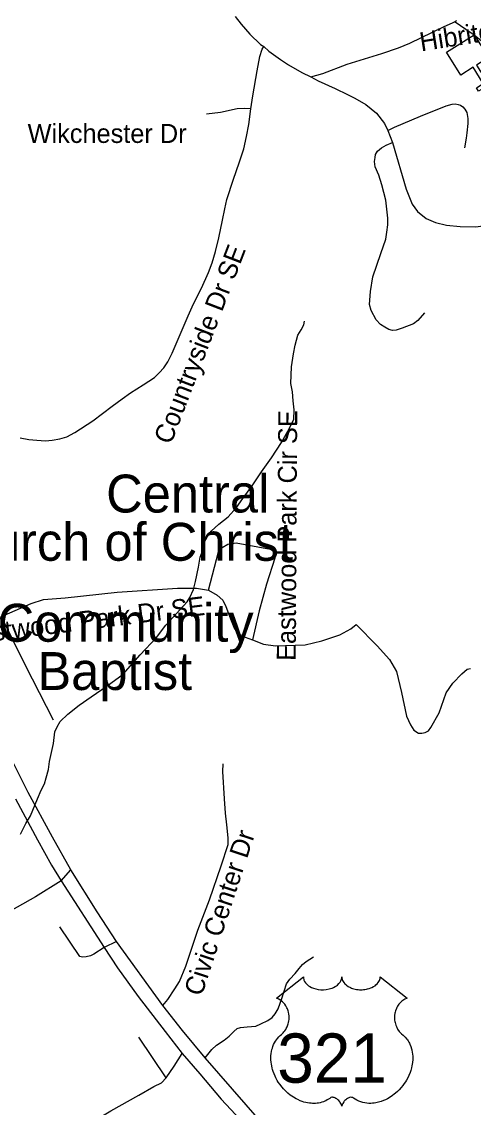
# Model space of a CAD drawing. Extents: x 1159738 to 1321356, y 736314 to 882035.
# Drawn here: x 1255384 to 1257173, y 783980 to 788278 of the extents above; entities that cross this region are included whole.
import ezdxf

# ---------------------------------------------------------------- set-up
doc = ezdxf.new("R2010")
doc.units = 0
for name, color, linetype in [('Exist Cultural Church CELL', 7, 'Continuous'), ('Exist Cultural Church Label', 7, 'Continuous'), ('Exist Hydrographic Misc Water Feature', 7, 'Continuous'), ('Exist Road Non-System Type 51', 7, 'Continuous'), ('Exist Road Non-System Type 51 Label', 7, 'Continuous'), ('Exist Road Primary US Divided Attributed', 7, 'Continuous'), ('Exist Road Primary US Shield CELL', 7, 'Continuous'), ('Exist Road Primary US Shield Number Label', 7, 'Continuous'), ('Exist Road Secondary Type 51 Attributed', 7, 'Continuous'), ('Exist Road Secondary Type 51 Label', 7, 'Continuous')]:
    doc.layers.add(name, color=color, linetype=linetype)

msp = doc.modelspace()

# ---------------------------------------------------------------- linework, layer by layer
at = {"layer": 'Exist Cultural Church CELL'}
msp.add_lwpolyline([(1257233.6, 788135.9), (1257185.5, 788105.5), (1257226, 788041.1), (1257253.1, 788058.1), (1257261.6, 788044.6), (1257234.5, 788027.5), (1257266.5, 787976.6), (1257252.9, 787968.1), (1257220.9, 788019), (1257193.8, 788002), (1257185.3, 788015.5), (1257212.4, 788032.5), (1257171.9, 788097), (1257123, 788066.4), (1257066.4, 788156.5), (1257177, 788226)], close=True, dxfattribs=at)
at = {"layer": 'Exist Hydrographic Misc Water Feature'}
msp.add_lwpolyline([(1255378.9, 785061.3), (1255400, 785102.8), (1255418.8, 785134.3), (1255446.5, 785201.6), (1255461.3, 785235.3), (1255474.1, 785261), (1255480.7, 785284.8), (1255489.5, 785316.6), (1255494.3, 785348.5), (1255510.2, 785420.1), (1255515.3, 785466.1), (1255523.9, 785485.8), (1255536.5, 785507.5), (1255567.2, 785536.7), (1255612.2, 785571.7), (1255659.1, 785604.5), (1255722.2, 785648.8), (1255785.5, 785695.2), (1255853.5, 785771.5), (1255917.4, 785839.9), (1255954.6, 785889), (1256024.6, 785965.2), (1256038.9, 785980.9), (1256049.5, 785998.6), (1256064.4, 786030.3), (1256073.1, 786062), (1256084.6, 786117.8), (1256091.6, 786157.6), (1256102.5, 786189.4), (1256107.1, 786215.3), (1256119.7, 786239), (1256134.3, 786260.6), (1256165, 786287.8), (1256201.9, 786316.9), (1256234.7, 786354.1), (1256259.7, 786389.5), (1256297.1, 786440.6), (1256334.4, 786495.6), (1256374, 786550.6), (1256413.5, 786611.6), (1256426.1, 786635.3), (1256445, 786668.8), (1256453.6, 786688.7), (1256461.9, 786702.4), (1256462.8, 786740.4), (1256459.8, 786776.5), (1256456.7, 786812.7), (1256449.6, 786844.9), (1256453.3, 786910.8), (1256460.6, 786962.7), (1256467.5, 786996.5), (1256478.5, 787036.2), (1256491.1, 787057.9), (1256501.5, 787077.7), (1256504, 787091.6)], dxfattribs=at)
at = {"layer": 'Exist Road Non-System Type 51'}
for p, q in [((1255956.1, 784096.6), (1255848.5, 784257.6)), ((1255987.8, 784142.8), (1256020.1, 784193.4)), ((1255956.1, 784096.6), (1255987.8, 784142.8))]:
    msp.add_line(p, q, dxfattribs=at)
for points in [[(1257100.9, 788276.4), (1257143.2, 788247.5), (1257176.8, 788225.3), (1257218.4, 788191.1), (1257296.3, 788125.2), (1257349.3, 788077.5), (1257394.9, 788037.9), (1257423.8, 788019.1), (1257451.3, 787994.9), (1257464.8, 787976.8), (1257470.1, 787962), (1257474.1, 787945.6), (1257477.4, 787922.8), (1257477.4, 787895.2), (1257473.4, 787875.8)], [(1256292.3, 787932.3), (1256299, 787984.4), (1256317.2, 788083.2), (1256327.2, 788140), (1256336.6, 788168.2), (1256343.3, 788179)], [(1255378.2, 786630.3), (1255412.5, 786623.6), (1255444, 786620.3), (1255478.9, 786618.9), (1255505.1, 786620.9), (1255535.3, 786626.3), (1255562.2, 786634.4), (1255595.1, 786651.8), (1255665.5, 786696.8), (1255741.9, 786755.1), (1255782.1, 786784.7), (1255815, 786808.9), (1255864.7, 786840.4), (1255910, 786869), (1255928.8, 786887.1), (1255947, 786907.3), (1255963.1, 786931.5), (1255979.8, 786965.1), (1256007.4, 787030.2), (1256042.9, 787113.5), (1256065, 787160.9), (1256095.9, 787222.7), (1256123.4, 787285.2), (1256138.8, 787323), (1256151.5, 787367.3), (1256164.9, 787421.8), (1256179, 787492.3), (1256188.4, 787536.6), (1256197.2, 787574.2), (1256222.6, 787653.8), (1256245.4, 787719), (1256263.5, 787774.1), (1256274.9, 787823.5), (1256283.6, 787870.5), (1256292.3, 787932.3)], [(1256292.3, 787932.3), (1256266.9, 787934.1), (1256238, 787932.8), (1256170.9, 787918.6), (1256115.9, 787911.9)], [(1256834.5, 787847.4), (1256861, 787859.7), (1256963.2, 787903.6), (1257065.9, 787945), (1257089.8, 787951.3), (1257101.5, 787951.8), (1257112.7, 787950.3), (1257121.9, 787947.4), (1257131.1, 787940.6), (1257138.9, 787930.8), (1257147.2, 787918.2), (1257151.6, 787894.3), (1257151.1, 787874.8), (1257147.7, 787837.3), (1257145.3, 787816.4), (1257137.5, 787778.8)], [(1256979.4, 787125.4), (1256953.6, 787094.2), (1256936.6, 787082), (1256890.8, 787064.5), (1256867, 787056.2), (1256853.4, 787055.2), (1256837.8, 787058.6), (1256822.7, 787067.9), (1256805.2, 787079.1), (1256788.1, 787097.1), (1256768.2, 787133.7), (1256761.8, 787158.5), (1256766.2, 787209.2), (1256775, 787268.1), (1256807.1, 787360.2), (1256827.1, 787416.7), (1256831, 787445), (1256833.9, 787473.7), (1256834.4, 787500), (1256831.5, 787523.4), (1256826.1, 787571.3), (1256810.5, 787632.2), (1256799.3, 787669.7), (1256784.2, 787703.3), (1256781.8, 787724.2), (1256783.8, 787740.3), (1256786.2, 787752), (1256793.5, 787764.9), (1256809.1, 787778.5), (1256828, 787788.8), (1256852.4, 787799.5)], [(1256124.3, 786027.3), (1256163.9, 786179.1), (1256178.7, 786196), (1256200.2, 786209), (1256233.7, 786214.2), (1256369.3, 786189.5), (1256384.1, 786180.4), (1256388.1, 786169.9), (1256386.8, 786154.3), (1256353.2, 786051.4), (1256325, 785945.9), (1256298.2, 785829.9)], [(1255191.1, 785872.2), (1255292.9, 785918.3), (1255422, 785973.9), (1255470.4, 785989.5), (1255556.3, 785997.3), (1255761.7, 786019.5), (1256000.8, 786035.1), (1256076, 786035.1), (1256124.3, 786027.3)], [(1256124.3, 786027.3), (1256158.5, 786007.1), (1256181.4, 785987.5), (1256192.1, 785962.8), (1256213.6, 785906.8), (1256227, 785874.2), (1256244.5, 785854.7), (1256268.6, 785841.6), (1256298.2, 785829.9)], [(1255292.9, 785918.3), (1255315.7, 785896.3), (1255344.6, 785836.5), (1255397.1, 785729.6), (1255509, 785513.5)], [(1256298.2, 785829.9), (1256342.5, 785813), (1256389.5, 785806.4), (1256506.3, 785810.4), (1256573.4, 785826), (1256643.9, 785850.1), (1256688.3, 785873.5), (1256708.8, 785890.6)], [(1256708.8, 785890.6), (1256791.9, 785807.2), (1256841.2, 785752.8), (1256868.1, 785705), (1256888.2, 785622.3), (1256908.4, 785528.8), (1256924.1, 785494), (1256937.5, 785472.3), (1256955.4, 785461.4), (1256968.9, 785461.4), (1256982.3, 785463.6), (1256995.8, 785470.1), (1257004.7, 785483.1), (1257038.4, 785541.9), (1257065.2, 785620.2), (1257092.1, 785659.3), (1257128, 785696.3), (1257148.2, 785713.7), (1257161.9, 785716.6)], [(1255943, 784383.3), (1255962.8, 784406.9), (1255990.8, 784448.2), (1256009.2, 784477.6), (1256034.2, 784538), (1256082.1, 784680.9), (1256127.5, 784801.3), (1256173.9, 784935.3), (1256201.8, 785020.4), (1256202.5, 785046.2), (1256196.6, 785098.5), (1256190.7, 785144.9), (1256187, 785200.9), (1256180.4, 785309.4), (1256182.6, 785339.5)], [(1255540.7, 784876.8), (1255579, 784920.2)], [(1255540.7, 784876.8), (1255439.1, 784813.4), (1255291.4, 784731.3)], [(1255710.4, 784612.3), (1255669.9, 784585.8), (1255656.7, 784579.1), (1255639, 784575.5), (1255624.3, 784574), (1255614.7, 784576.9), (1255534.5, 784694)], [(1255759.7, 784636.6), (1255710.4, 784612.3)], [(1256111.4, 784175.4), (1256137.1, 784209.2), (1256155.5, 784225.4), (1256185.7, 784246.1), (1256205.6, 784261.5), (1256224, 784279.9), (1256237.2, 784291.7), (1256250.5, 784296.2), (1256277.7, 784298.4), (1256311.6, 784301.3), (1256330.7, 784310.9), (1256358.7, 784323.4), (1256376.3, 784335.9), (1256388.6, 784349.7), (1256399.6, 784369.6), (1256414.3, 784410.8), (1256432.7, 784468.3), (1256446.7, 784486.7), (1256467.3, 784509.5), (1256483.5, 784529.4), (1256496, 784544.9), (1256511.5, 784556.7), (1256540.2, 784575.1)], [(1255602, 783885.7), (1255736.7, 783965.2), (1255848.1, 784028.3), (1255908, 784061.6), (1255937.4, 784077), (1255956.1, 784096.6)]]:
    msp.add_lwpolyline(points, dxfattribs=at)
at = {"layer": 'Exist Road Primary US Divided Attributed'}
for points in [[(1256326.9, 783927), (1256111.4, 784175.4), (1256020.7, 784284.4), (1255943, 784383.3), (1255759.7, 784636.6), (1255683.2, 784754.3), (1255579, 784920.2), (1255505.4, 785048.9), (1255409.1, 785226), (1255337, 785371.1), (1255253.6, 785532.1), (1255166.7, 785714.4), (1255144.5, 785758.2), (1255037, 785979.7), (1254900.5, 786258.5), (1254752.6, 786556.6), (1254651, 786761.2), (1254574, 786916.1), (1254464.3, 787134.7), (1254340.1, 787387.7), (1254244.7, 787573.2), (1254139.2, 787789.1), (1254097.8, 787873.2)], [(1255360, 785201.6), (1255446.5, 785038.1), (1255502.3, 784938.3), (1255540.7, 784876.8), (1255710.4, 784612.3), (1255763.4, 784531.6), (1255845.1, 784418.5), (1255952.7, 784279.3), (1256020.1, 784193.4), (1256089.2, 784112.8), (1256174.4, 784012.2), (1256306.9, 783869.3)]]:
    msp.add_lwpolyline(points, dxfattribs=at)
at = {"layer": 'Exist Road Primary US Shield CELL'}
msp.add_lwpolyline([(1256500, 784496), (1256500.3, 784491.6), (1256501.4, 784486.4), (1256502.2, 784483.7), (1256504.7, 784478.5), (1256508.7, 784472.5), (1256514.3, 784466.5), (1256520.6, 784461.3), (1256524.9, 784458.5), (1256532.1, 784454.6), (1256540.4, 784451.2), (1256549.5, 784448.5), (1256558.9, 784446.6), (1256569.1, 784445.5), (1256579.2, 784445.3), (1256590.1, 784446.1), (1256602.2, 784448.5), (1256607.8, 784449.9), (1256614, 784452), (1256619.8, 784454.4), (1256626.1, 784457.8), (1256631.2, 784461.1), (1256635.2, 784464), (1256640.8, 784469.4), (1256645.3, 784475), (1256647.2, 784478.1), (1256648.8, 784481.1), (1256651.1, 784487.5), (1256651.7, 784490.4), (1256652.1, 784496.2), (1256652.5, 784491.3), (1256653, 784488.2), (1256653.8, 784485.2), (1256655.1, 784482), (1256657.3, 784477.5), (1256659.8, 784473.7), (1256664.6, 784468.1), (1256667.5, 784465.4), (1256670.2, 784463.2), (1256677.5, 784458.2), (1256685.9, 784453.9), (1256690, 784452.1), (1256694.3, 784450.6), (1256699.7, 784449), (1256705.3, 784447.7), (1256710.8, 784446.7), (1256716.5, 784445.9), (1256722.2, 784445.5), (1256726.9, 784445.3), (1256732.7, 784445.4), (1256738.1, 784445.7), (1256743.5, 784446.3), (1256749.5, 784447.3), (1256754.4, 784448.4), (1256760.8, 784450.1), (1256766.6, 784452.2), (1256771.6, 784454.4), (1256778.2, 784457.8), (1256783.6, 784461.2), (1256787.5, 784464.3), (1256792.1, 784468.6), (1256796.5, 784473.7), (1256799.1, 784477.4), (1256800.9, 784481.2), (1256802.6, 784485.2), (1256803.6, 784489.5), (1256804.1, 784493.2), (1256804.2, 784496.3), (1256910.5, 784411.7), (1256908, 784410.7), (1256902.2, 784407.9), (1256897.6, 784405.2), (1256890.3, 784400), (1256887.2, 784397.2), (1256884, 784394.3), (1256881.2, 784391.1), (1256878.6, 784388.2), (1256875.5, 784383.9), (1256872.8, 784379.6), (1256870.1, 784374.9), (1256868.1, 784370.8), (1256864.8, 784362.3), (1256863.3, 784356.9), (1256862.3, 784352.3), (1256861, 784342.8), (1256860.7, 784338.3), (1256860.7, 784333.9), (1256860.9, 784329.1), (1256861.4, 784324.6), (1256862.2, 784319.9), (1256863, 784315.8), (1256864.3, 784310.7), (1256866.2, 784304.8), (1256868.5, 784299.1), (1256873.3, 784289.8), (1256879.6, 784280.4), (1256884, 784275.1), (1256888.4, 784270.6), (1256895, 784265.1), (1256898.5, 784262), (1256902.6, 784257.9), (1256909.3, 784250.1), (1256912, 784246.5), (1256914.7, 784242.4), (1256917.2, 784238.2), (1256919.7, 784233.7), (1256921.7, 784229.7), (1256925.5, 784220.6), (1256928.2, 784211.8), (1256929.5, 784207.1), (1256931.4, 784196.7), (1256932.2, 784191.6), (1256933, 784181.4), (1256933, 784169.1), (1256932.1, 784157.4), (1256929.9, 784143.8), (1256928.1, 784135.6), (1256925.3, 784126.1), (1256922.6, 784117.9), (1256917.7, 784105.8), (1256913.4, 784097), (1256907.8, 784086.7), (1256904, 784080.5), (1256899.5, 784073.8), (1256894, 784066.1), (1256887.4, 784058), (1256879.6, 784049.4), (1256873.2, 784043), (1256865, 784035.6), (1256859.9, 784031.5), (1256852.8, 784026.1), (1256843, 784019.5), (1256833.3, 784014), (1256825.1, 784009.8), (1256817.8, 784006.6), (1256808.4, 784003), (1256792.7, 783998.7), (1256787, 783997.5), (1256780.2, 783996.5), (1256773.9, 783995.9), (1256767.7, 783995.5), (1256759.5, 783995.5), (1256751.2, 783996.1), (1256743.5, 783997.3), (1256735.4, 783999), (1256726.9, 784001.5), (1256719.2, 784004.5), (1256711.4, 784008.3), (1256698.3, 784016.6), (1256694.5, 784018.6), (1256692.3, 784019.2), (1256687.2, 784019.4), (1256682.5, 784018.4), (1256677.6, 784016.5), (1256674.6, 784014.9), (1256670.7, 784012.3), (1256667.7, 784009.9), (1256664.1, 784006.5), (1256661.5, 784003.6), (1256659.6, 784001.3), (1256655.9, 783995.5), (1256654.6, 783992.7), (1256653.2, 783989.2), (1256652, 783983.9), (1256650.3, 783990.5), (1256648.4, 783994.9), (1256646.1, 783998.7), (1256643.8, 784002), (1256640.1, 784006.3), (1256636.7, 784009.5), (1256632.7, 784012.8), (1256628.5, 784015.3), (1256625, 784017.1), (1256621.9, 784018.3), (1256618.1, 784019.2), (1256614.9, 784019.5), (1256612.4, 784019.4), (1256608.8, 784018.6), (1256604, 784015.2), (1256599.5, 784012), (1256594.5, 784008.9), (1256588.6, 784005.8), (1256584.3, 784003.8), (1256579.1, 784001.8), (1256573.1, 783999.8), (1256566.6, 783998.1), (1256559.9, 783996.8), (1256554, 783995.8), (1256547.6, 783995.2), (1256541.9, 783995.1), (1256535.9, 783995.1), (1256530.4, 783995.6), (1256523.9, 783996.1), (1256515.9, 783997.3), (1256509.2, 783998.8), (1256502.2, 784000.7), (1256495, 784003), (1256487.2, 784005.9), (1256477.6, 784010.1), (1256470.9, 784013.6), (1256460.3, 784019.7), (1256447.8, 784028.3), (1256438.4, 784035.9), (1256431.6, 784042.1), (1256421.5, 784052.4), (1256415.5, 784059.1), (1256406.2, 784071.2), (1256400.2, 784079.9), (1256396.4, 784086.3), (1256390.7, 784096.6), (1256387.6, 784103.1), (1256383.6, 784112.5), (1256380.4, 784121.1), (1256377.8, 784129.3), (1256376.4, 784134.5), (1256374.4, 784143.6), (1256373.2, 784150), (1256372, 784158.9), (1256371.3, 784168.3), (1256371.2, 784176.9), (1256371.4, 784184), (1256372.2, 784192.4), (1256373.6, 784201.2), (1256375.3, 784208.8), (1256376.9, 784214.3), (1256379.1, 784220.9), (1256382.1, 784228.3), (1256385.6, 784235.3), (1256389, 784241.2), (1256393.2, 784247.4), (1256397.3, 784252.8), (1256402.8, 784258.7), (1256408.4, 784264.1), (1256413.6, 784268.3), (1256419.7, 784274.3), (1256422.9, 784278), (1256426.8, 784283.1), (1256429.9, 784287.8), (1256432.3, 784292), (1256435.6, 784298.2), (1256437.5, 784302.8), (1256440, 784310), (1256441.2, 784315), (1256442.4, 784321.5), (1256443.2, 784327.6), (1256443.6, 784335.2), (1256443.4, 784341.5), (1256442.6, 784348.8), (1256441.2, 784355.8), (1256439.5, 784362), (1256436.9, 784369), (1256434.5, 784374.2), (1256430.4, 784381.1), (1256425.9, 784387.6), (1256421.2, 784392.9), (1256416.5, 784397.6), (1256412, 784401.1), (1256407.7, 784404.2), (1256402.3, 784407.5), (1256397, 784410), (1256393.8, 784411.3)], close=True, dxfattribs=at)
at = {"layer": 'Exist Road Secondary Type 51 Attributed'}
for points in [[(1256229.8, 788297.8), (1256253, 788267.4), (1256288.3, 788228.3), (1256330.5, 788187.9), (1256343.3, 788179), (1256363.6, 788160.5), (1256408.7, 788127.6), (1256441.2, 788106.2), (1256493.7, 788076.5), (1256529.8, 788059.7)], [(1256529.8, 788059.7), (1256576.5, 788073), (1256673.5, 788109.2), (1256810.9, 788151.4), (1256877.3, 788173.9), (1256921.9, 788192.6), (1257054.8, 788257.8), (1257093, 788275), (1257108.1, 788281.9)], [(1256529.8, 788059.7), (1256559, 788043.7), (1256625.7, 788013), (1256674.7, 787989.4), (1256703.9, 787974.5), (1256747.7, 787949.2), (1256789.6, 787915.1), (1256820.6, 787875.2), (1256834.5, 787847.4), (1256852.4, 787799.5), (1256906.9, 787614.6), (1256931.2, 787555.6), (1256952.1, 787526), (1256986.7, 787498.3), (1257023.7, 787482.7), (1257067, 787471.5), (1257120.9, 787466.7), (1257183.5, 787465.7), (1257360.2, 787490.1), (1257392.3, 787486.7), (1257417.1, 787479.3), (1257463.7, 787454.1), (1257529.7, 787403.4)]]:
    msp.add_lwpolyline(points, dxfattribs=at)

# ---------------------------------------------------------------- texts
at = {"layer": 'Exist Cultural Church Label'}
for s, p in [('Central', (1255718.5, 786334.5)), ('Church of Christ', (1255009.5, 786143.5)), ('Community', (1255288.7, 785823)), ('Baptist', (1255446.2, 785631.9))]:
    msp.add_text(s, height=150, dxfattribs=at).set_placement(p)
at = {"layer": 'Exist Road Non-System Type 51 Label'}
msp.add_text('Wikchester Dr', height=75, dxfattribs=at).set_placement((1255407.5, 787797.6))
for s, rotation, p in [('Countryside Dr SE', 68.9817, (1255975, 786600.3)), ('Eastwood Park Cir SE', 89.6504, (1256469.5, 785746.9)), ('Eastwood Park Dr SE', 7.0795, (1255150.4, 785809.7)), ('Civic Center Dr', 71.7813, (1256096.6, 784416))]:
    msp.add_text(s, height=75, rotation=rotation, dxfattribs=at).set_placement(p)
at = {"layer": 'Exist Road Primary US Shield Number Label'}
msp.add_text('321', height=195, dxfattribs=at).set_placement((1256396.2, 784077.3))
at = {"layer": 'Exist Road Secondary Type 51 Label'}
msp.add_text('Hibriten Mountain Rd', height=75, rotation=8.966, dxfattribs=at).set_placement((1256966.4, 788159.9))

doc.saveas('drawing.dxf')
